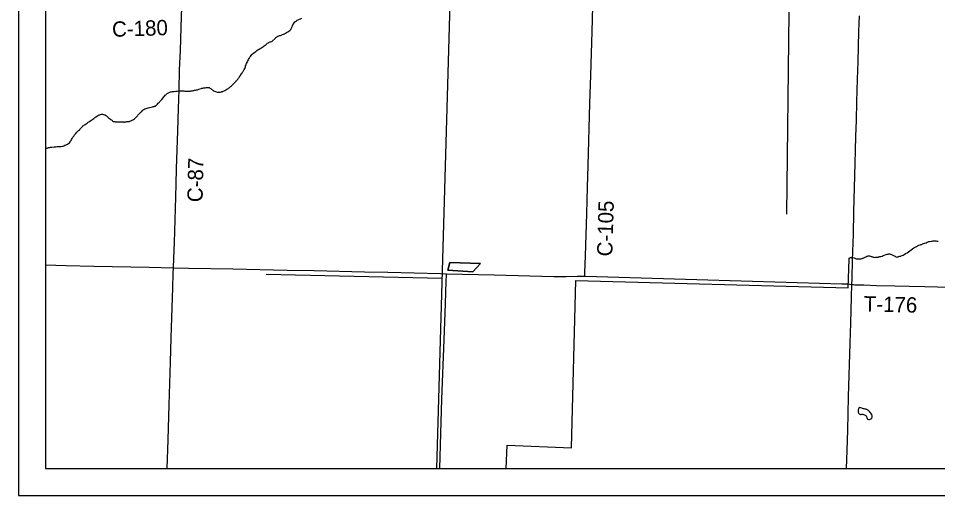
# Model space of a CAD drawing. Extents: x 0 to 64.8, y -5 to 22.
# Drawn here: x 2 to 5.41, y 14 to 15.77 of the extents above; entities that cross this region are included whole.
import ezdxf

# ---------------------------------------------------------------- set-up
doc = ezdxf.new("R2010")
doc.units = 0
for name, color, linetype in [('GM_X_Adjacent_County', 7, 'Continuous'), ('GM_X_County', 7, 'Continuous'), ('GM_X_County_Road', 7, 'Continuous'), ('GM_X_County_Road_Text', 7, 'Continuous'), ('GM_X_Minor_Lake', 7, 'Continuous'), ('GM_X_Minor_River', 7, 'Continuous'), ('GM_X_Township', 7, 'Continuous'), ('GM_X_Township_Road', 7, 'Continuous'), ('GM_X_Township_Road_Text', 7, 'Continuous'), ('GM_X_US_Route', 7, 'Continuous'), ('SH_Data', 7, 'Continuous')]:
    doc.layers.add(name, color=color, linetype=linetype)

msp = doc.modelspace()

# ---------------------------------------------------------------- linework, layer by layer
at = {"layer": 'GM_X_Adjacent_County'}
msp.add_lwpolyline([(2.1, 19.9176), (2.1, 14.1), (8.9, 14.1), (8.9, 19.781)], dxfattribs=at)
at = {"layer": 'GM_X_County'}
msp.add_lwpolyline([(2.1, 19.9176), (2.1, 14.1), (8.9, 14.1), (8.9, 19.781)], dxfattribs=at)
at = {"layer": 'GM_X_County_Road'}
for points in [[(4.1013, 14.8145), (4.1014, 14.8184), (4.1015, 14.8276), (4.1031, 14.8896), (4.1081, 15.0448), (4.1111, 15.1441), (4.1134, 15.2247), (4.1201, 15.4543), (4.1232, 15.5598), (4.128, 15.7212), (4.1306, 15.8142), (4.1309, 15.8224)], [(2.5753, 14.8452), (2.5765, 14.8805), (2.5785, 14.9395), (2.5836, 15.1073), (2.5849, 15.1569), (2.5866, 15.2129), (2.5909, 15.3527), (2.5938, 15.4365), (2.596, 15.5048), (2.5982, 15.5794), (2.6008, 15.6508), (2.6052, 15.7782), (2.6062, 15.8089)], [(2.1, 14.8558), (2.1772, 14.8542), (2.2798, 14.8518), (2.4848, 14.847), (2.5753, 14.8452)], [(2.552, 14.1), (2.5554, 14.2065), (2.5594, 14.3369), (2.5642, 14.4953), (2.5669, 14.5854), (2.5728, 14.7718), (2.5746, 14.8246), (2.5753, 14.8452)], [(2.5753, 14.8452), (2.6309, 14.8441), (2.7956, 14.8408), (2.9975, 14.8368), (3.097, 14.8347), (3.2834, 14.8306), (3.3704, 14.8287), (3.5661, 14.8238), (3.588, 14.8232)], [(3.588, 14.8232), (3.765, 14.8185), (3.9856, 14.813), (4.0322, 14.8129), (4.0726, 14.8142), (4.1013, 14.8145)], [(4.1013, 14.8145), (4.1036, 14.8145), (4.5572, 14.8007), (5.0543, 14.7862), (5.0707, 14.786), (5.0775, 14.7856), (5.0835, 14.7849), (5.0916, 14.7837)]]:
    msp.add_lwpolyline(points, dxfattribs=at)
at = {"layer": 'GM_X_Minor_Lake'}
for points in [[(3.5998, 14.8646), (3.5935, 14.8359), (3.6861, 14.83)], [(3.5998, 14.8646), (3.7142, 14.8613), (3.6861, 14.83), (3.5935, 14.8359), (3.5998, 14.8646)], [(3.6861, 14.83), (3.7142, 14.8613), (3.5998, 14.8646)], [(5.1182, 14.3268), (5.1156, 14.3203), (5.1152, 14.3184), (5.1147, 14.3162), (5.1143, 14.3135), (5.1146, 14.3109), (5.115, 14.309), (5.1161, 14.307), (5.1175, 14.3051), (5.1194, 14.3032), (5.1216, 14.302), (5.1239, 14.3015), (5.1262, 14.3011), (5.1281, 14.3018), (5.1323, 14.3017), (5.1353, 14.3009), (5.1387, 14.3001), (5.1413, 14.2989), (5.1436, 14.2973), (5.1451, 14.2954), (5.1461, 14.2923), (5.1468, 14.2896), (5.1479, 14.2866), (5.1494, 14.2835), (5.1539, 14.283), (5.1566, 14.2829), (5.1589, 14.2837), (5.1618, 14.2846)], [(5.1618, 14.2846), (5.1623, 14.2847), (5.165, 14.2869), (5.1658, 14.2888), (5.1663, 14.2911), (5.1667, 14.293), (5.1668, 14.296), (5.1661, 14.2987), (5.165, 14.3006), (5.1639, 14.3025), (5.1613, 14.3053), (5.1594, 14.3083), (5.1565, 14.3122), (5.1531, 14.3153), (5.1513, 14.3165), (5.1494, 14.3177), (5.1475, 14.3189), (5.1452, 14.3197), (5.143, 14.3201), (5.1407, 14.3209), (5.1373, 14.3217), (5.1347, 14.3222), (5.1313, 14.323), (5.1279, 14.3242), (5.1245, 14.3251), (5.1182, 14.3268)]]:
    msp.add_lwpolyline(points, dxfattribs=at)
at = {"layer": 'GM_X_Minor_River'}
for points in [[(3.5518, 14.1), (3.6372, 17.0786)], [(4.8507, 15.0442), (4.859, 15.793)], [(2.9396, 15.6841), (2.9531, 15.6972), (2.9551, 15.6994), (2.9578, 15.7009), (2.9597, 15.7024), (2.9617, 15.7039), (2.9639, 15.7046), (2.9659, 15.7053), (2.9686, 15.7064), (2.972, 15.7074), (2.977, 15.7088), (2.98, 15.7103), (2.9835, 15.7121), (2.9873, 15.7135), (2.9908, 15.7154), (2.9943, 15.7176), (2.9989, 15.7209), (3.0035, 15.723), (3.0066, 15.7256), (3.0105, 15.7297), (3.0121, 15.7327), (3.0133, 15.7346), (3.0145, 15.7376), (3.0161, 15.7402), (3.0169, 15.7429), (3.0185, 15.7459), (3.0205, 15.7504), (3.0233, 15.7541), (3.026, 15.7571), (3.0279, 15.7586), (3.031, 15.7615), (3.0337, 15.7634), (3.0376, 15.7652), (3.0422, 15.767), (3.0468, 15.7692), (3.0518, 15.771)], [(2.8483, 15.6063), (2.8499, 15.6101), (2.8519, 15.6138), (2.8539, 15.618), (2.8559, 15.6221), (2.8582, 15.6262), (2.861, 15.6296), (2.8634, 15.633), (2.8657, 15.636), (2.8688, 15.6389), (2.8719, 15.6415), (2.8766, 15.6448), (2.8805, 15.6482), (2.8847, 15.6507), (2.8886, 15.6533), (2.8928, 15.6559), (2.8963, 15.6581), (2.8994, 15.6603), (2.9064, 15.6647), (2.9087, 15.6661), (2.9114, 15.6687), (2.9153, 15.6709), (2.9176, 15.6724), (2.9196, 15.6739), (2.9227, 15.6768), (2.9246, 15.6779), (2.9273, 15.6798), (2.9308, 15.6816), (2.9331, 15.6831), (2.935, 15.6838), (2.9396, 15.6841)], [(2.5645, 15.4976), (2.568, 15.4983), (2.5722, 15.499), (2.5783, 15.4996), (2.5836, 15.5002), (2.5894, 15.5009), (2.5955, 15.5011), (2.6012, 15.5014), (2.6069, 15.5012), (2.6111, 15.5015), (2.6141, 15.5014), (2.6168, 15.501), (2.6195, 15.5009), (2.6217, 15.5005), (2.6236, 15.5005), (2.6259, 15.5), (2.6282, 15.5), (2.6309, 15.5003), (2.6335, 15.5002), (2.6366, 15.5006), (2.6393, 15.5013), (2.6423, 15.5016), (2.6454, 15.5019), (2.6485, 15.5026), (2.6511, 15.5029), (2.6538, 15.5036), (2.6569, 15.5039), (2.6611, 15.5049), (2.6638, 15.5056), (2.6665, 15.5063), (2.6699, 15.5074), (2.6776, 15.5103), (2.6807, 15.511), (2.6845, 15.512), (2.6872, 15.5123), (2.6902, 15.513), (2.6933, 15.5133), (2.6964, 15.5136), (2.6994, 15.5143), (2.7025, 15.5143), (2.7044, 15.5142), (2.7074, 15.5138), (2.7104, 15.5118), (2.7127, 15.5102), (2.7149, 15.5086), (2.7172, 15.5071), (2.719, 15.5051), (2.7213, 15.5039), (2.7243, 15.502), (2.728, 15.5), (2.7307, 15.4992), (2.7345, 15.4979), (2.739, 15.4971), (2.7436, 15.4966), (2.7466, 15.4965), (2.7493, 15.4965), (2.7528, 15.4979), (2.7551, 15.4986), (2.7578, 15.4997), (2.7601, 15.5004), (2.7631, 15.5018), (2.7662, 15.5033), (2.7697, 15.5051), (2.7732, 15.5073), (2.7763, 15.5091), (2.7794, 15.511), (2.7817, 15.5128), (2.784, 15.5151), (2.7868, 15.5176), (2.7903, 15.5206), (2.798, 15.5277), (2.8008, 15.5306), (2.8027, 15.5325), (2.8047, 15.5343), (2.8062, 15.5362), (2.8082, 15.5384), (2.8101, 15.5403), (2.8117, 15.5425), (2.8141, 15.5444), (2.8152, 15.5466), (2.8168, 15.5489), (2.8184, 15.5511), (2.82, 15.5538), (2.8216, 15.5568), (2.8235, 15.559), (2.8251, 15.5616), (2.8267, 15.5642), (2.8283, 15.5665), (2.8299, 15.5691), (2.8322, 15.5721), (2.8334, 15.5744), (2.8346, 15.5762), (2.8362, 15.5785), (2.8374, 15.5811), (2.8394, 15.5849), (2.8406, 15.5875), (2.8418, 15.5905), (2.843, 15.5939), (2.8446, 15.598), (2.8463, 15.6029), (2.8483, 15.6063)], [(2.2721, 15.3937), (2.2756, 15.3971), (2.2795, 15.3996), (2.2826, 15.4018), (2.2849, 15.4029), (2.2876, 15.4055), (2.293, 15.4088), (2.2954, 15.4103), (2.2977, 15.4114), (2.3, 15.4125), (2.3023, 15.4132), (2.305, 15.4143), (2.308, 15.4149), (2.31, 15.4149), (2.3126, 15.4145), (2.3156, 15.4136), (2.3191, 15.4132), (2.3217, 15.4123), (2.3236, 15.4115), (2.327, 15.4088), (2.3288, 15.4069), (2.3314, 15.4041), (2.3344, 15.4014), (2.3374, 15.3991), (2.3419, 15.3955), (2.3449, 15.3936), (2.3475, 15.3916), (2.3494, 15.3908), (2.3532, 15.3884), (2.3554, 15.388), (2.3581, 15.3876), (2.3604, 15.3871), (2.363, 15.3867), (2.3661, 15.3866), (2.3695, 15.3869), (2.3741, 15.3864), (2.3783, 15.3864), (2.3825, 15.3863), (2.3859, 15.3862), (2.3893, 15.3861), (2.3916, 15.386), (2.3939, 15.386), (2.3962, 15.3863), (2.3992, 15.387), (2.4023, 15.3873), (2.4054, 15.388), (2.4092, 15.3883), (2.4118, 15.3882), (2.4138, 15.3886), (2.4172, 15.3904), (2.4199, 15.3915), (2.4276, 15.3959), (2.4303, 15.3977), (2.4319, 15.3996), (2.435, 15.4018), (2.4374, 15.4044), (2.4397, 15.4066), (2.4413, 15.4085), (2.4436, 15.4111), (2.446, 15.4137), (2.4487, 15.417), (2.4503, 15.4189), (2.4526, 15.4208), (2.455, 15.4234), (2.4573, 15.4252), (2.4604, 15.4289), (2.4631, 15.4308), (2.4658, 15.4322), (2.4689, 15.4345), (2.4735, 15.4359), (2.4774, 15.4373), (2.482, 15.4387), (2.4866, 15.4401), (2.4919, 15.4411), (2.4969, 15.4422), (2.5004, 15.4432), (2.5031, 15.4436), (2.505, 15.4443), (2.508, 15.4453), (2.51, 15.4468), (2.5119, 15.4479), (2.5139, 15.4498), (2.5162, 15.4524), (2.5186, 15.4554), (2.5205, 15.4576), (2.5236, 15.4602), (2.5252, 15.4624), (2.5272, 15.4647), (2.5295, 15.4673), (2.5315, 15.4699), (2.537, 15.4762), (2.5397, 15.4788), (2.5421, 15.4822), (2.5448, 15.4852), (2.5471, 15.487), (2.5502, 15.49), (2.5534, 15.493), (2.5564, 15.4944), (2.5588, 15.4959), (2.5622, 15.4969), (2.5645, 15.4976)], [(2.1, 15.287), (2.1001, 15.287), (2.1024, 15.2878), (2.1051, 15.2888), (2.107, 15.2895), (2.1093, 15.2899), (2.1112, 15.291), (2.1143, 15.2917), (2.117, 15.292), (2.1193, 15.2927), (2.1219, 15.293), (2.1246, 15.2933), (2.1326, 15.2939), (2.1357, 15.2942), (2.1395, 15.2945), (2.1433, 15.2948), (2.149, 15.295), (2.154, 15.2949), (2.159, 15.2956), (2.1632, 15.2959), (2.1658, 15.2969), (2.1689, 15.298), (2.1728, 15.2998), (2.1774, 15.3016), (2.1816, 15.3038), (2.1855, 15.3064), (2.1894, 15.3093), (2.1917, 15.3123), (2.1937, 15.3146), (2.1953, 15.3176), (2.1969, 15.3213), (2.1993, 15.3247), (2.202, 15.3292), (2.2052, 15.3341), (2.2087, 15.3389), (2.213, 15.3434), (2.2169, 15.3478), (2.2205, 15.3516), (2.2232, 15.3542), (2.2263, 15.3568), (2.2283, 15.3594), (2.2302, 15.3612), (2.2318, 15.3631), (2.233, 15.365), (2.2349, 15.3672), (2.2373, 15.3698), (2.2396, 15.3717), (2.2423, 15.3735), (2.245, 15.3753), (2.2481, 15.3772), (2.2512, 15.3798), (2.2555, 15.3819), (2.2593, 15.3849), (2.264, 15.3878), (2.2682, 15.3911), (2.2721, 15.3937)], [(5.0811, 14.8772), (5.0819, 14.8806), (5.0866, 14.8835), (5.0892, 14.8834), (5.0923, 14.8834), (5.0957, 14.8829), (5.0998, 14.8821), (5.1029, 14.8812), (5.1055, 14.88), (5.1077, 14.8788), (5.1096, 14.8784), (5.1123, 14.878), (5.1142, 14.8779), (5.1169, 14.8779), (5.1195, 14.8782), (5.1226, 14.8785), (5.1256, 14.8788), (5.1294, 14.8799), (5.1314, 14.8806), (5.134, 14.8813), (5.1363, 14.8824), (5.1387, 14.8835), (5.141, 14.8849), (5.1437, 14.8864), (5.1467, 14.8878), (5.1494, 14.8889), (5.1517, 14.8892), (5.154, 14.8896), (5.1574, 14.8895), (5.1612, 14.8883), (5.1635, 14.8875), (5.1657, 14.8866), (5.1684, 14.8854), (5.1706, 14.8846), (5.1725, 14.8842), (5.1748, 14.8838), (5.1786, 14.8841), (5.1824, 14.8844), (5.1858, 14.8847), (5.1885, 14.885), (5.1904, 14.8853), (5.1923, 14.8857), (5.1954, 14.8867), (5.1992, 14.8874), (5.2034, 14.8888), (5.2076, 14.8903), (5.2115, 14.8917), (5.2145, 14.8931), (5.2222, 14.8956), (5.2256, 14.8963), (5.2291, 14.8966), (5.2317, 14.8965), (5.234, 14.8961), (5.2363, 14.8957), (5.2385, 14.8949), (5.2408, 14.8937), (5.2434, 14.8925), (5.2464, 14.8909), (5.2483, 14.8897), (5.2517, 14.8877), (5.2543, 14.8858), (5.2585, 14.8849), (5.2608, 14.8856), (5.2638, 14.8863), (5.2661, 14.887), (5.2699, 14.8877), (5.2726, 14.8884), (5.2749, 14.8891), (5.278, 14.8902), (5.2814, 14.8916), (5.2853, 14.8942), (5.2907, 14.8979), (5.2965, 14.9012), (5.3015, 14.9048), (5.3061, 14.9085), (5.3112, 14.9122), (5.317, 14.9159), (5.3216, 14.9188), (5.3262, 14.9214), (5.3308, 14.9239), (5.3354, 14.9261), (5.3401, 14.9287), (5.3447, 14.9301), (5.3477, 14.9311), (5.3508, 14.9322), (5.3535, 14.9337), (5.3569, 14.9347), (5.3612, 14.9369), (5.3669, 14.9383), (5.3711, 14.9401), (5.375, 14.9415), (5.3776, 14.9426), (5.3799, 14.943), (5.3883, 14.9443), (5.3914, 14.945), (5.3948, 14.9453), (5.3997, 14.9452), (5.4035, 14.9447), (5.4073, 14.9442), (5.4115, 14.9438)], [(3.8089, 14.1), (3.8126, 14.1871), (4.0516, 14.1776), (4.0671, 14.7982), (5.0779, 14.7709), (5.0811, 14.8772)], [(2.919, 14.8221), (3.572, 14.8064)]]:
    msp.add_lwpolyline(points, dxfattribs=at)
at = {"layer": 'GM_X_Township'}
msp.add_lwpolyline([(2.1, 19.9176), (2.1, 14.1), (5.5757, 14.1)], dxfattribs=at)
at = {"layer": 'GM_X_Township_Road'}
for points in [[(3.5637, 14.1), (3.5672, 14.2305), (3.571, 14.3579), (3.5793, 14.5784), (3.5841, 14.7119), (3.587, 14.7958), (3.5878, 14.8176), (3.588, 14.8232)], [(5.0916, 14.7837), (5.0972, 14.7827), (5.102, 14.7823), (5.1069, 14.782), (5.1364, 14.7815), (5.1829, 14.78), (5.2511, 14.7787), (5.3037, 14.7774), (5.3626, 14.7759), (5.4091, 14.7751), (5.4525, 14.7739), (5.5114, 14.7729), (5.6021, 14.7717)]]:
    msp.add_lwpolyline(points, dxfattribs=at)
at = {"layer": 'GM_X_US_Route'}
msp.add_lwpolyline([(5.0718, 14.1), (5.0738, 14.1677), (5.076, 14.2423), (5.0777, 14.3044), (5.0793, 14.3666), (5.0851, 14.5655), (5.0874, 14.6401), (5.0901, 14.7364), (5.0916, 14.7837), (5.0923, 14.8048), (5.0944, 14.8732), (5.0972, 14.9695), (5.0993, 15.0534), (5.1027, 15.1871), (5.1038, 15.2337), (5.1052, 15.2803), (5.1067, 15.3332), (5.1085, 15.3922), (5.1103, 15.4606), (5.1127, 15.5445), (5.1146, 15.6098), (5.1178, 15.7217), (5.1189, 15.7512), (5.1199, 15.7798)], dxfattribs=at)
at = {"layer": 'SH_Data'}
for p, q in [((2, 21), (2, 14)), ((2.1, 20.9), (2.1, 14.1)), ((2.1, 14.1), (8.9, 14.1)), ((2.1, 14.1), (2.1, 14.1)), ((2, 14), (9, 14))]:
    msp.add_line(p, q, dxfattribs=at)

# ---------------------------------------------------------------- texts
at = {"layer": 'GM_X_County_Road_Text'}
for s, rotation, p in [('C-180', 1.9275, (2.3484, 15.7016)), ('C-87', 88.6274, (2.683, 15.0881)), ('C-105', 88.3517, (4.2029, 14.8868))]:
    msp.add_text(s, height=0.05682, rotation=rotation, dxfattribs=at).set_placement(p)
at = {"layer": 'GM_X_Township_Road_Text'}
msp.add_text('T-176', height=0.05682, rotation=358.6043, dxfattribs=at).set_placement((5.1351, 14.6834))

doc.saveas('drawing.dxf')
